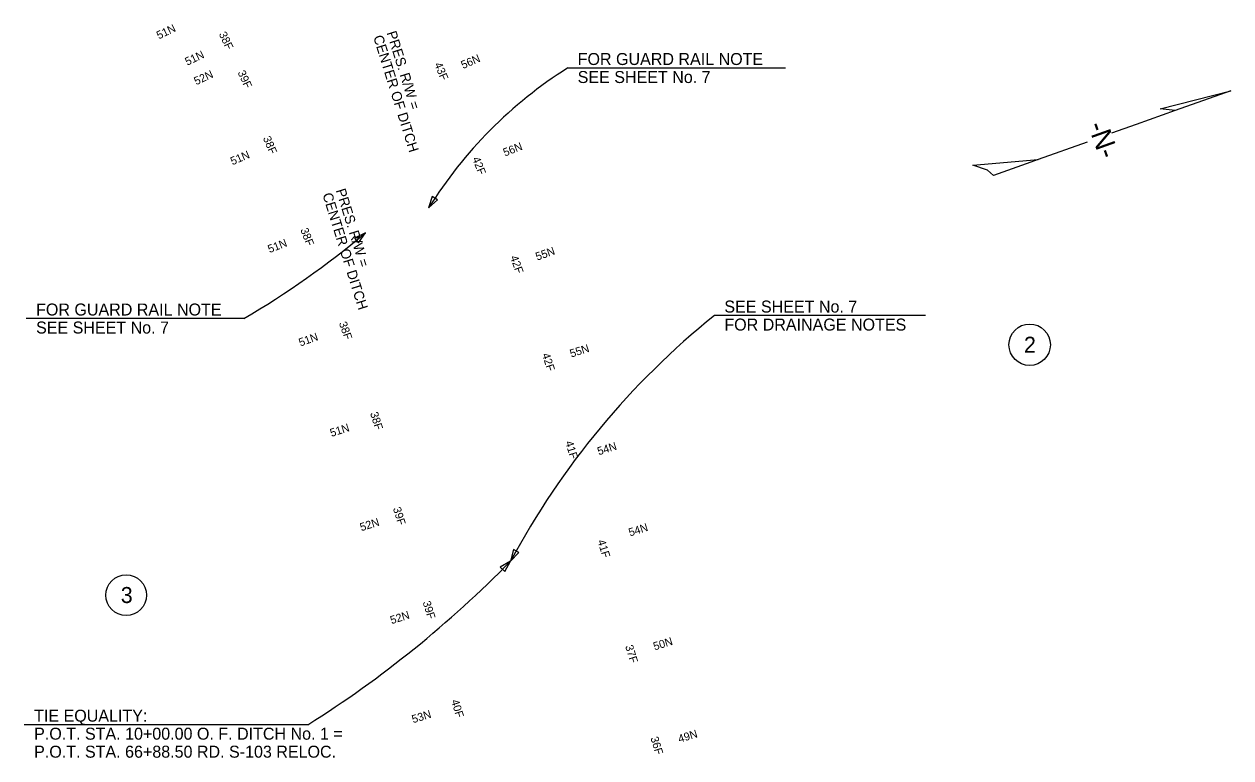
# Model space of a CAD drawing. Extents: x 1964849 to 1967422, y 1116563 to 1122211.
# Drawn here: x 1965800 to 1966404, y 1121844 to 1122211 of the extents above; entities that cross this region are included whole.
import ezdxf

# ---------------------------------------------------------------- set-up
doc = ezdxf.new("R2010")
doc.units = 0
for name, color, linetype in [('RD_EX_DV_TX_Prop', 7, 'Continuous'), ('RD_EX_Misc', 7, 'Continuous'), ('RD_EX_RW_TX', 7, 'Continuous'), ('RD_HC_Data', 7, 'Continuous'), ('RD_PD_TX_CstnLmt', 7, 'Continuous'), ('RD_TX_Drainage', 7, 'Continuous'), ('RD_TX_Misc1', 7, 'Continuous')]:
    doc.layers.add(name, color=color, linetype=linetype)

msp = doc.modelspace()

# ---------------------------------------------------------------- linework, layer by layer
at = {"layer": 'RD_EX_DV_TX_Prop'}
for centre, radius in [((1966303, 1122050.52), 10.35), ((1965851.32, 1121925.33), 10.18)]:
    msp.add_circle(centre, radius, dxfattribs=at)
at = {"layer": 'RD_EX_Misc'}
for p, q in [((1966368.2, 1122168.4), (1966403.6, 1122177.49)), ((1966403.6, 1122177.49), (1966375.68, 1122167.53)), ((1966375.68, 1122167.53), (1966356.33, 1122160.63)), ((1966375.68, 1122167.53), (1966368.2, 1122168.4)), ((1966356.33, 1122160.63), (1966343.99, 1122156.23)), ((1966331.68, 1122151.83), (1966307.28, 1122143.13)), ((1966274.62, 1122140.24), (1966307.28, 1122143.13)), ((1966303.59, 1122141.81), (1966284.89, 1122135.15)), ((1966307.28, 1122143.13), (1966303.59, 1122141.81))]:
    msp.add_line(p, q, dxfattribs=at)
msp.add_lwpolyline([(1966284.89, 1122135.15), (1966281.88, 1122137.83), (1966274.62, 1122140.24)], dxfattribs=at)
at = {"layer": 'RD_HC_Data'}
msp.add_line((1965942.2, 1121860.58), (1965800.31, 1121860.58), dxfattribs=at)
msp.add_lwpolyline([(1966040.58, 1121937.1), (1966043.53, 1121942.33), (1966038.36, 1121939.27)], close=True, dxfattribs=at)
msp.add_arc((1965643.51, 1122334.48), 560.18, 302.2228, 315.56909, dxfattribs=at)
at = {"layer": 'RD_TX_Drainage'}
msp.add_line((1966250.88, 1122065.1), (1966145.38, 1122065.1), dxfattribs=at)
msp.add_lwpolyline([(1966044.9, 1121948.17), (1966043.53, 1121942.33), (1966047.63, 1121946.7)], close=True, dxfattribs=at)
msp.add_arc((1966395.59, 1121753.89), 399.32, 128.79831, 151.84205, dxfattribs=at)
at = {"layer": 'RD_TX_Misc1'}
for p, q in [((1966180.98, 1122188.85), (1966072.05, 1122188.85)), ((1965910.21, 1122063.62), (1965801.28, 1122063.62))]:
    msp.add_line(p, q, dxfattribs=at)
for points in [[(1966004.28, 1122124.63), (1966002.53, 1122118.89), (1966006.92, 1122122.99)], [(1965967.47, 1122101.47), (1965970.92, 1122106.38), (1965965.48, 1122103.86)]]:
    msp.add_lwpolyline(points, close=True, dxfattribs=at)
for centre, radius, start, end in [((1966190.3, 1122001.84), 221.27, 122.30524, 148.05938), ((1965679.91, 1122455.07), 454.17, 300.46957, 309.84733)]:
    msp.add_arc(centre, radius, start, end, dxfattribs=at)

# ---------------------------------------------------------------- texts
at = {"layer": 'RD_EX_DV_TX_Prop'}
for s, p in [('2', (1966300.16, 1122046.53)), ('3', (1965848.62, 1121921.4))]:
    msp.add_text(s, height=8, dxfattribs=at).set_placement(p)
at = {"layer": 'RD_EX_Misc'}
msp.add_text('-N-', height=10, rotation=289.63025, dxfattribs=at).set_placement((1966332.02, 1122160.22))
at = {"layer": 'RD_EX_RW_TX'}
for s, p in [('PRES. R/W = ', (1965981.47, 1122206.48)), ('CENTER OF DITCH', (1965974.79, 1122204.39)), ('PRES. R/W = ', (1965956.07, 1122127.7)), ('CENTER OF DITCH', (1965949.39, 1122125.62))]:
    msp.add_text(s, height=5, rotation=287.32637, dxfattribs=at).set_placement(p)
at = {"layer": 'RD_HC_Data'}
for s, p in [('TIE EQUALITY:', (1965805.31, 1121862.08)), ('P.O.T. STA. 10+00.00 O. F. DITCH No. 1 =', (1965805.31, 1121853.08)), ('P.O.T. STA. 66+88.50 RD. S-103 RELOC.', (1965805.31, 1121844.08))]:
    msp.add_text(s, height=6, dxfattribs=at).set_placement(p)
at = {"layer": 'RD_PD_TX_CstnLmt'}
for s, rotation, p in [('38F', 295.14766, (1965897.56, 1122205.89)), ('43F', 293.11766, (1966005.27, 1122190.7)), ('39F', 294.86766, (1965906.93, 1122186.6)), ('38F', 293.11766, (1965919.62, 1122153.81)), ('42F', 291.36766, (1966024.26, 1122143.58)), ('38F', 291.36766, (1965938.33, 1122108.03)), ('42F', 289.61766, (1966043.22, 1122094.34)), ('38F', 289.61766, (1965957.62, 1122061.3)), ('42F', 287.86766, (1966059.15, 1122045.69)), ('38F', 287.86766, (1965973.21, 1122016.26)), ('41F', 287.35688, (1966070.76, 1122001.79)), ('39F', 287.35688, (1965984.63, 1121968.69)), ('41F', 287.35688, (1966086.87, 1121952.4)), ('39F', 287.35688, (1965999.5, 1121921.77)), ('37F', 287.35688, (1966100.73, 1121899.78)), ('40F', 287.35688, (1966013.71, 1121872.49)), ('36F', 287.35688, (1966113.36, 1121853.94))]:
    msp.add_text(s, height=4, rotation=rotation, dxfattribs=at).set_placement(p)
at = {"layer": 'RD_TX_Drainage'}
for s, rotation, p in [('51N', 25.69206, (1965867.66, 1122203.12)), ('51N', 25.14766, (1965881.88, 1122189.98)), ('56N', 23.11766, (1966019.74, 1122188.32)), ('52N', 24.86766, (1965886.36, 1122180.21)), ('51N', 23.11766, (1965904.48, 1122140.21)), ('56N', 21.36766, (1966040.7, 1122144.58)), ('51N', 21.36766, (1965923.04, 1122096.29)), ('55N', 19.61766, (1966056.83, 1122092.53)), ('51N', 19.61766, (1965938.44, 1122049.61)), ('55N', 17.86766, (1966073.87, 1122044.07)), ('51N', 17.86766, (1965953.97, 1122004.41)), ('54N', 17.35688, (1966087.59, 1121995.23)), ('52N', 17.35688, (1965968.9, 1121957.27)), ('54N', 17.35688, (1966103.2, 1121954.66)), ('52N', 17.35688, (1965984.02, 1121910.81)), ('50N', 17.35688, (1966115.55, 1121897.69)), ('53N', 17.35688, (1965994.85, 1121861.27)), ('49N', 17.35688, (1966127.96, 1121851.46))]:
    msp.add_text(s, height=4, rotation=rotation, dxfattribs=at).set_placement(p)
for s, p in [('SEE SHEET No. 7', (1966150.38, 1122066.6)), ('FOR DRAINAGE NOTES', (1966150.38, 1122057.6))]:
    msp.add_text(s, height=6, dxfattribs=at).set_placement(p)
at = {"layer": 'RD_TX_Misc1'}
for s, p in [('FOR GUARD RAIL NOTE', (1966077.05, 1122190.35)), ('SEE SHEET No. 7', (1966077.05, 1122181.35)), ('FOR GUARD RAIL NOTE', (1965806.28, 1122065.12)), ('SEE SHEET No. 7', (1965806.28, 1122056.12))]:
    msp.add_text(s, height=6, dxfattribs=at).set_placement(p)

doc.saveas('drawing.dxf')
